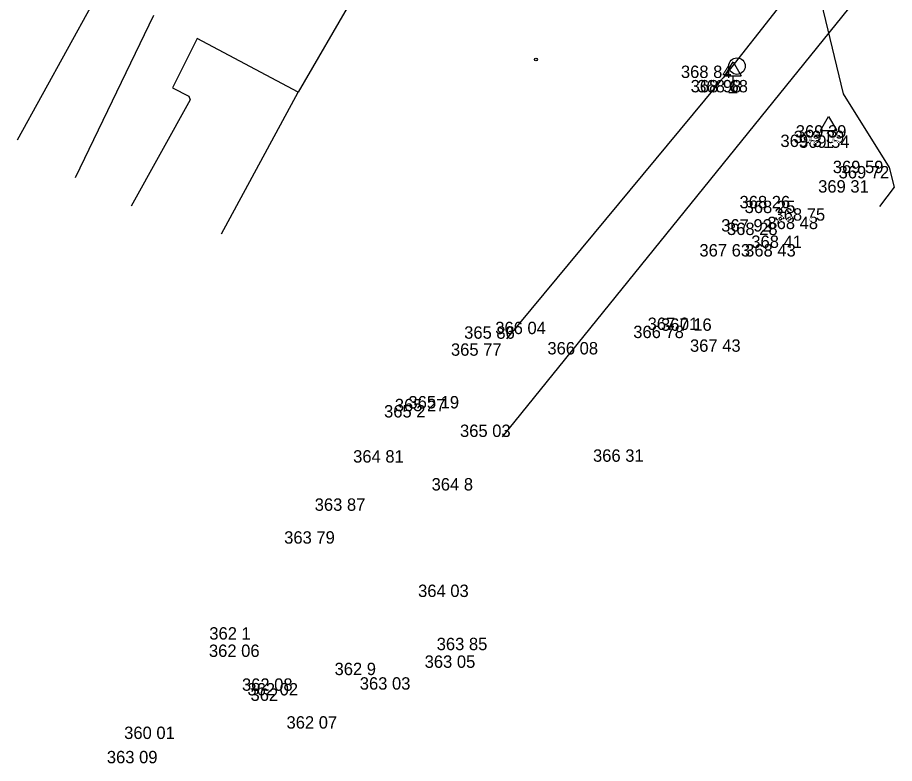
# Model space of a CAD drawing. Extents: x -688316 to -688024, y -973785 to -973591.
# Drawn here: x -688146.8 to -688093.7, y -973764.3 to -973719.2 of the extents above; entities that cross this region are included whole.
import ezdxf

# ---------------------------------------------------------------- set-up
doc = ezdxf.new("R2010")
doc.units = 0
for name, color, linetype in [('Vrstva 10', 7, 'Continuous'), ('Vrstva 27', 7, 'Continuous'), ('Vrstva 3', 7, 'Continuous'), ('Vrstva 34', 7, 'Continuous'), ('Vrstva 5', 7, 'Continuous'), ('Vrstva 58', 7, 'Continuous')]:
    doc.layers.add(name, color=color, linetype=linetype)

# ---------------------------------------------------------------- blocks, each defined once
blk = doc.blocks.new('B_NESP')
at = {"layer": 'Vrstva 58'}
blk.add_circle((0, 0), 0.875, dxfattribs=at)
blk = doc.blocks.new('DZ')
at = {"layer": 'Vrstva 34'}
for p, q in [((-5, 10), (0, 18.5)), ((0, 18.5), (5, 10)), ((-5, 10), (5, 10)), ((0, 0), (0, 10)), ((-2.49, 0), (2.49, 0))]:
    blk.add_line(p, q, dxfattribs=at)
blk = doc.blocks.new('SAK')
at = {"layer": 'Vrstva 27'}
blk.add_circle((0, 0), 5, dxfattribs=at)

msp = doc.modelspace()

# ---------------------------------------------------------------- linework, layer by layer
at = {"layer": 'Vrstva 10'}
msp.add_line((-688117.48, -973744.56), (-688096.49, -973718.61), dxfattribs=at)
at = {"layer": 'Vrstva 3'}
for points in [[(-688094.03, -973728.25), (-688096.82, -973723.78), (-688098.3, -973717.64), (-688099.11, -973714.05), (-688102.09, -973711.56)], [(-688094.03, -973728.25), (-688096.82, -973723.78), (-688098.3, -973717.64), (-688099.11, -973714.05), (-688102.09, -973711.56)], [(-688094.03, -973728.25), (-688096.82, -973723.78), (-688098.3, -973717.64), (-688099.11, -973714.05), (-688102.09, -973711.56)], [(-688094.03, -973728.25), (-688096.82, -973723.78), (-688098.3, -973717.64), (-688099.11, -973714.05), (-688102.09, -973711.56)], [(-688094.62, -973730.61), (-688093.73, -973729.44), (-688094.03, -973728.25)], [(-688094.62, -973730.61), (-688093.73, -973729.44), (-688094.03, -973728.25)], [(-688094.62, -973730.61), (-688093.73, -973729.44), (-688094.03, -973728.25)], [(-688094.62, -973730.61), (-688093.73, -973729.44), (-688094.03, -973728.25)]]:
    msp.add_lwpolyline(points, dxfattribs=at)
at = {"layer": 'Vrstva 5'}
for p, q in [((-688118.65, -973704.4), (-688129.85, -973723.67)), ((-688146.85, -973726.56), (-688142.31, -973718.32)), ((-688138.61, -973719.03), (-688143.36, -973728.87)), ((-688135.96, -973720.43), (-688137.47, -973723.41)), ((-688129.85, -973723.67), (-688135.96, -973720.43)), ((-688137.47, -973723.41), (-688136.48, -973723.93)), ((-688136.48, -973723.93), (-688136.4, -973724.15)), ((-688134.5, -973732.26), (-688129.85, -973723.67)), ((-688136.4, -973724.15), (-688139.97, -973730.58))]:
    msp.add_line(p, q, dxfattribs=at)
msp.add_lwpolyline([(-688100.74, -973717.32), (-688100.7, -973717.61), (-688100.61, -973718.36), (-688104.1, -973722.82), (-688104.28, -973723.02), (-688104.45, -973723.22), (-688117.23, -973738.61)], dxfattribs=at)

# ---------------------------------------------------------------- block references
at = {"layer": 'Vrstva 27', "xscale": 0.1, "yscale": 0.10000000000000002}
msp.add_blockref('SAK', (-688103.27, -973722.1), dxfattribs=at)
at = {"layer": 'Vrstva 34', "xscale": 0.1, "yscale": 0.10000000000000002}
for p in [(-688103.51, -973723.69), (-688103.51, -973723.69), (-688103.51, -973723.69), (-688103.51, -973723.69), (-688097.72, -973727), (-688097.72, -973727), (-688097.72, -973727), (-688097.72, -973727)]:
    msp.add_blockref('DZ', p, dxfattribs=at)
at = {"layer": 'Vrstva 58', "xscale": 0.1, "yscale": 0.10000000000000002}
msp.add_blockref('B_NESP', (-688115.45, -973721.7), dxfattribs=at)
msp.add_blockref('B_NESP', (-688115.45, -973721.7), dxfattribs=at)
msp.add_blockref('B_NESP', (-688115.45, -973721.7), dxfattribs=at)
msp.add_blockref('B_NESP', (-688115.45, -973721.7), dxfattribs=at)

# ---------------------------------------------------------------- texts
at = {"layer": 'Vrstva 3'}
for s, p in [('368 84 ', (-688106.666, -973722.82)), ('368 84 ', (-688106.666, -973722.82)), ('368 84 ', (-688106.666, -973722.82)), ('368 84 ', (-688106.666, -973722.82)), ('368 84 ', (-688106.666, -973722.82)), ('368 84 ', (-688106.666, -973722.82)), ('368 84 ', (-688106.666, -973722.82)), ('368 98 ', (-688106.076, -973723.69)), ('368 98 ', (-688106.076, -973723.69)), ('368 98 ', (-688106.076, -973723.69)), ('368 98 ', (-688106.076, -973723.69)), ('368 98 ', (-688106.076, -973723.69)), ('368 98 ', (-688106.076, -973723.69)), ('368 98 ', (-688106.076, -973723.69)), ('368 68 ', (-688105.675, -973723.69)), ('368 68 ', (-688105.675, -973723.69)), ('368 68 ', (-688105.675, -973723.69)), ('368 68 ', (-688105.675, -973723.69)), ('368 68 ', (-688105.675, -973723.69)), ('368 68 ', (-688105.675, -973723.69)), ('368 68 ', (-688105.675, -973723.69)), ('369 39 ', (-688099.708, -973726.43)), ('369 39 ', (-688099.708, -973726.43)), ('369 39 ', (-688099.708, -973726.43)), ('369 39 ', (-688099.708, -973726.43)), ('369 39 ', (-688099.708, -973726.43)), ('369 39 ', (-688099.708, -973726.43)), ('369 39 ', (-688099.708, -973726.43)), ('369 3  ', (-688100.637, -973727)), ('369 3  ', (-688100.637, -973727)), ('369 3  ', (-688100.637, -973727)), ('369 3  ', (-688100.637, -973727)), ('369 3  ', (-688100.637, -973727)), ('369 3  ', (-688100.637, -973727)), ('369 3  ', (-688100.637, -973727)), ('369 39 ', (-688099.838, -973726.76)), ('369 39 ', (-688099.838, -973726.76)), ('369 39 ', (-688099.838, -973726.76)), ('369 39 ', (-688099.838, -973726.76)), ('369 39 ', (-688099.838, -973726.76)), ('369 39 ', (-688099.838, -973726.76)), ('369 39 ', (-688099.838, -973726.76)), ('369 54 ', (-688099.516, -973727.05)), ('369 54 ', (-688099.516, -973727.05)), ('369 54 ', (-688099.516, -973727.05)), ('369 54 ', (-688099.516, -973727.05)), ('369 54 ', (-688099.516, -973727.05)), ('369 54 ', (-688099.516, -973727.05)), ('369 54 ', (-688099.516, -973727.05)), ('369 59 ', (-688097.466, -973728.58)), ('369 59 ', (-688097.466, -973728.58)), ('369 59 ', (-688097.466, -973728.58)), ('369 59 ', (-688097.466, -973728.58)), ('369 59 ', (-688097.466, -973728.58)), ('369 59 ', (-688097.466, -973728.58)), ('369 59 ', (-688097.466, -973728.58)), ('369 72 ', (-688097.116, -973728.9)), ('369 72 ', (-688097.116, -973728.9)), ('369 72 ', (-688097.116, -973728.9)), ('369 72 ', (-688097.116, -973728.9)), ('369 72 ', (-688097.116, -973728.9)), ('369 72 ', (-688097.116, -973728.9)), ('369 72 ', (-688097.116, -973728.9)), ('369 31 ', (-688098.353, -973729.76)), ('369 31 ', (-688098.353, -973729.76)), ('369 31 ', (-688098.353, -973729.76)), ('369 31 ', (-688098.353, -973729.76)), ('369 31 ', (-688098.353, -973729.76)), ('369 31 ', (-688098.353, -973729.76)), ('369 31 ', (-688098.353, -973729.76)), ('368 26 ', (-688103.116, -973730.71)), ('368 26 ', (-688103.116, -973730.71)), ('368 26 ', (-688103.116, -973730.71)), ('368 26 ', (-688103.116, -973730.71)), ('368 26 ', (-688103.116, -973730.71)), ('368 26 ', (-688103.116, -973730.71)), ('368 26 ', (-688103.116, -973730.71)), ('368 25 ', (-688102.806, -973731)), ('368 25 ', (-688102.806, -973731)), ('368 25 ', (-688102.806, -973731)), ('368 25 ', (-688102.806, -973731)), ('368 25 ', (-688102.806, -973731)), ('368 25 ', (-688102.806, -973731)), ('368 25 ', (-688102.806, -973731)), ('368 75 ', (-688100.996, -973731.46)), ('368 75 ', (-688100.996, -973731.46)), ('368 75 ', (-688100.996, -973731.46)), ('368 75 ', (-688100.996, -973731.46)), ('368 75 ', (-688100.996, -973731.46)), ('368 75 ', (-688100.996, -973731.46)), ('368 75 ', (-688100.996, -973731.46)), ('367 92 ', (-688104.226, -973732.12)), ('367 92 ', (-688104.226, -973732.12)), ('367 92 ', (-688104.226, -973732.12)), ('367 92 ', (-688104.226, -973732.12)), ('367 92 ', (-688104.226, -973732.12)), ('367 92 ', (-688104.226, -973732.12)), ('367 92 ', (-688104.226, -973732.12)), ('368 48 ', (-688101.426, -973731.97)), ('368 48 ', (-688101.426, -973731.97)), ('368 48 ', (-688101.426, -973731.97)), ('368 48 ', (-688101.426, -973731.97)), ('368 48 ', (-688101.426, -973731.97)), ('368 48 ', (-688101.426, -973731.97)), ('368 48 ', (-688101.426, -973731.97)), ('368 28 ', (-688103.876, -973732.33)), ('368 28 ', (-688103.876, -973732.33)), ('368 28 ', (-688103.876, -973732.33)), ('368 28 ', (-688103.876, -973732.33)), ('368 28 ', (-688103.876, -973732.33)), ('368 28 ', (-688103.876, -973732.33)), ('368 28 ', (-688103.876, -973732.33)), ('368 41 ', (-688102.401, -973733.11)), ('368 41 ', (-688102.401, -973733.11)), ('368 41 ', (-688102.401, -973733.11)), ('368 41 ', (-688102.401, -973733.11)), ('368 41 ', (-688102.401, -973733.11)), ('368 41 ', (-688102.401, -973733.11)), ('368 41 ', (-688102.401, -973733.11)), ('367 63 ', (-688105.545, -973733.63)), ('367 63 ', (-688105.545, -973733.63)), ('367 63 ', (-688105.545, -973733.63)), ('367 63 ', (-688105.545, -973733.63)), ('367 63 ', (-688105.545, -973733.63)), ('367 63 ', (-688105.545, -973733.63)), ('367 63 ', (-688105.545, -973733.63)), ('368 43 ', (-688102.776, -973733.63)), ('368 43 ', (-688102.776, -973733.63)), ('368 43 ', (-688102.776, -973733.63)), ('368 43 ', (-688102.776, -973733.63)), ('368 43 ', (-688102.776, -973733.63)), ('368 43 ', (-688102.776, -973733.63)), ('368 43 ', (-688102.776, -973733.63)), ('367 01 ', (-688108.681, -973738.08)), ('367 01 ', (-688108.681, -973738.08)), ('367 01 ', (-688108.681, -973738.08)), ('367 01 ', (-688108.681, -973738.08)), ('367 01 ', (-688108.681, -973738.08)), ('367 01 ', (-688108.681, -973738.08)), ('367 01 ', (-688108.681, -973738.08)), ('367 16 ', (-688107.871, -973738.13)), ('367 16 ', (-688107.871, -973738.13)), ('367 16 ', (-688107.871, -973738.13)), ('367 16 ', (-688107.871, -973738.13)), ('367 16 ', (-688107.871, -973738.13)), ('367 16 ', (-688107.871, -973738.13)), ('367 16 ', (-688107.871, -973738.13)), ('365 86 ', (-688119.796, -973738.61)), ('365 86 ', (-688119.796, -973738.61)), ('365 86 ', (-688119.796, -973738.61)), ('365 86 ', (-688119.796, -973738.61)), ('365 86 ', (-688119.796, -973738.61)), ('365 86 ', (-688119.796, -973738.61)), ('365 86 ', (-688119.796, -973738.61)), ('366 04 ', (-688117.913, -973738.33)), ('366 04 ', (-688117.913, -973738.33)), ('366 04 ', (-688117.913, -973738.33)), ('366 04 ', (-688117.913, -973738.33)), ('366 04 ', (-688117.913, -973738.33)), ('366 04 ', (-688117.913, -973738.33)), ('366 04 ', (-688117.913, -973738.33)), ('366 78 ', (-688109.553, -973738.57)), ('366 78 ', (-688109.553, -973738.57)), ('366 78 ', (-688109.553, -973738.57)), ('366 78 ', (-688109.553, -973738.57)), ('366 78 ', (-688109.553, -973738.57)), ('366 78 ', (-688109.553, -973738.57)), ('366 78 ', (-688109.553, -973738.57)), ('365 77 ', (-688120.596, -973739.64)), ('365 77 ', (-688120.596, -973739.64)), ('365 77 ', (-688120.596, -973739.64)), ('365 77 ', (-688120.596, -973739.64)), ('365 77 ', (-688120.596, -973739.64)), ('365 77 ', (-688120.596, -973739.64)), ('365 77 ', (-688120.596, -973739.64)), ('366 08 ', (-688114.753, -973739.56)), ('366 08 ', (-688114.753, -973739.56)), ('366 08 ', (-688114.753, -973739.56)), ('366 08 ', (-688114.753, -973739.56)), ('366 08 ', (-688114.753, -973739.56)), ('366 08 ', (-688114.753, -973739.56)), ('366 08 ', (-688114.753, -973739.56)), ('367 43 ', (-688106.116, -973739.4)), ('367 43 ', (-688106.116, -973739.4)), ('367 43 ', (-688106.116, -973739.4)), ('367 43 ', (-688106.116, -973739.4)), ('367 43 ', (-688106.116, -973739.4)), ('367 43 ', (-688106.116, -973739.4)), ('367 43 ', (-688106.116, -973739.4)), ('365 19 ', (-688123.171, -973742.83)), ('365 19 ', (-688123.171, -973742.83)), ('365 19 ', (-688123.171, -973742.83)), ('365 19 ', (-688123.171, -973742.83)), ('365 19 ', (-688123.171, -973742.83)), ('365 19 ', (-688123.171, -973742.83)), ('365 19 ', (-688123.171, -973742.83)), ('365 2  ', (-688124.647, -973743.38)), ('365 2  ', (-688124.647, -973743.38)), ('365 2  ', (-688124.647, -973743.38)), ('365 2  ', (-688124.647, -973743.38)), ('365 2  ', (-688124.647, -973743.38)), ('365 2  ', (-688124.647, -973743.38)), ('365 2  ', (-688124.647, -973743.38)), ('365 27 ', (-688123.996, -973743)), ('365 27 ', (-688123.996, -973743)), ('365 27 ', (-688123.996, -973743)), ('365 27 ', (-688123.996, -973743)), ('365 27 ', (-688123.996, -973743)), ('365 27 ', (-688123.996, -973743)), ('365 27 ', (-688123.996, -973743)), ('365 03 ', (-688120.046, -973744.56)), ('365 03 ', (-688120.046, -973744.56)), ('365 03 ', (-688120.046, -973744.56)), ('365 03 ', (-688120.046, -973744.56)), ('365 03 ', (-688120.046, -973744.56)), ('365 03 ', (-688120.046, -973744.56)), ('365 03 ', (-688120.046, -973744.56)), ('364 81 ', (-688126.521, -973746.11)), ('364 81 ', (-688126.521, -973746.11)), ('364 81 ', (-688126.521, -973746.11)), ('364 81 ', (-688126.521, -973746.11)), ('364 81 ', (-688126.521, -973746.11)), ('364 81 ', (-688126.521, -973746.11)), ('364 81 ', (-688126.521, -973746.11)), ('366 31 ', (-688111.991, -973746.06)), ('366 31 ', (-688111.991, -973746.06)), ('366 31 ', (-688111.991, -973746.06)), ('366 31 ', (-688111.991, -973746.06)), ('366 31 ', (-688111.991, -973746.06)), ('366 31 ', (-688111.991, -973746.06)), ('366 31 ', (-688111.991, -973746.06)), ('364 8  ', (-688121.767, -973747.8)), ('364 8  ', (-688121.767, -973747.8)), ('364 8  ', (-688121.767, -973747.8)), ('364 8  ', (-688121.767, -973747.8)), ('364 8  ', (-688121.767, -973747.8)), ('364 8  ', (-688121.767, -973747.8)), ('364 8  ', (-688121.767, -973747.8)), ('363 87 ', (-688128.849, -973749.03)), ('363 87 ', (-688128.849, -973749.03)), ('363 87 ', (-688128.849, -973749.03)), ('363 87 ', (-688128.849, -973749.03)), ('363 87 ', (-688128.849, -973749.03)), ('363 87 ', (-688128.849, -973749.03)), ('363 87 ', (-688128.849, -973749.03)), ('363 79 ', (-688130.699, -973751.02)), ('363 79 ', (-688130.699, -973751.02)), ('363 79 ', (-688130.699, -973751.02)), ('363 79 ', (-688130.699, -973751.02)), ('363 79 ', (-688130.699, -973751.02)), ('363 79 ', (-688130.699, -973751.02)), ('363 79 ', (-688130.699, -973751.02)), ('364 03 ', (-688122.586, -973754.25)), ('364 03 ', (-688122.586, -973754.25)), ('364 03 ', (-688122.586, -973754.25)), ('364 03 ', (-688122.586, -973754.25)), ('364 03 ', (-688122.586, -973754.25)), ('364 03 ', (-688122.586, -973754.25)), ('364 03 ', (-688122.586, -973754.25)), ('362 1  ', (-688135.233, -973756.83)), ('362 1  ', (-688135.233, -973756.83)), ('362 1  ', (-688135.233, -973756.83)), ('362 1  ', (-688135.233, -973756.83)), ('362 1  ', (-688135.233, -973756.83)), ('362 1  ', (-688135.233, -973756.83)), ('362 1  ', (-688135.233, -973756.83)), ('363 85 ', (-688121.459, -973757.47)), ('363 85 ', (-688121.459, -973757.47)), ('363 85 ', (-688121.459, -973757.47)), ('363 85 ', (-688121.459, -973757.47)), ('363 85 ', (-688121.459, -973757.47)), ('363 85 ', (-688121.459, -973757.47)), ('363 85 ', (-688121.459, -973757.47)), ('362 06 ', (-688135.256, -973757.88)), ('362 06 ', (-688135.256, -973757.88)), ('362 06 ', (-688135.256, -973757.88)), ('362 06 ', (-688135.256, -973757.88)), ('362 06 ', (-688135.256, -973757.88)), ('362 06 ', (-688135.256, -973757.88)), ('362 06 ', (-688135.256, -973757.88)), ('363 05 ', (-688122.189, -973758.54)), ('363 05 ', (-688122.189, -973758.54)), ('363 05 ', (-688122.189, -973758.54)), ('363 05 ', (-688122.189, -973758.54)), ('363 05 ', (-688122.189, -973758.54)), ('363 05 ', (-688122.189, -973758.54)), ('363 05 ', (-688122.189, -973758.54)), ('362 9  ', (-688127.647, -973758.98)), ('362 9  ', (-688127.647, -973758.98)), ('362 9  ', (-688127.647, -973758.98)), ('362 9  ', (-688127.647, -973758.98)), ('362 9  ', (-688127.647, -973758.98)), ('362 9  ', (-688127.647, -973758.98)), ('362 9  ', (-688127.647, -973758.98)), ('362 08 ', (-688133.256, -973759.93)), ('362 08 ', (-688133.256, -973759.93)), ('362 08 ', (-688133.256, -973759.93)), ('362 08 ', (-688133.256, -973759.93)), ('362 08 ', (-688133.256, -973759.93)), ('362 08 ', (-688133.256, -973759.93)), ('362 08 ', (-688133.256, -973759.93)), ('363 03 ', (-688126.119, -973759.86)), ('363 03 ', (-688126.119, -973759.86)), ('363 03 ', (-688126.119, -973759.86)), ('363 03 ', (-688126.119, -973759.86)), ('363 03 ', (-688126.119, -973759.86)), ('363 03 ', (-688126.119, -973759.86)), ('363 03 ', (-688126.119, -973759.86)), ('362 02 ', (-688132.926, -973760.21)), ('362 02 ', (-688132.926, -973760.21)), ('362 02 ', (-688132.926, -973760.21)), ('362 02 ', (-688132.926, -973760.21)), ('362 02 ', (-688132.926, -973760.21)), ('362 02 ', (-688132.926, -973760.21)), ('362 02 ', (-688132.926, -973760.21)), ('362    ', (-688132.737, -973760.54)), ('362    ', (-688132.737, -973760.54)), ('362    ', (-688132.737, -973760.54)), ('362    ', (-688132.737, -973760.54)), ('362    ', (-688132.737, -973760.54)), ('362    ', (-688132.737, -973760.54)), ('362    ', (-688132.737, -973760.54)), ('362 07 ', (-688130.556, -973762.22)), ('362 07 ', (-688130.556, -973762.22)), ('362 07 ', (-688130.556, -973762.22)), ('362 07 ', (-688130.556, -973762.22)), ('362 07 ', (-688130.556, -973762.22)), ('362 07 ', (-688130.556, -973762.22)), ('362 07 ', (-688130.556, -973762.22)), ('360 01 ', (-688140.391, -973762.85)), ('360 01 ', (-688140.391, -973762.85)), ('360 01 ', (-688140.391, -973762.85)), ('360 01 ', (-688140.391, -973762.85)), ('360 01 ', (-688140.391, -973762.85)), ('360 01 ', (-688140.391, -973762.85)), ('360 01 ', (-688140.391, -973762.85)), ('363 09 ', (-688141.439, -973764.32)), ('363 09 ', (-688141.439, -973764.32)), ('363 09 ', (-688141.439, -973764.32)), ('363 09 ', (-688141.439, -973764.32)), ('363 09 ', (-688141.439, -973764.32)), ('363 09 ', (-688141.439, -973764.32)), ('363 09 ', (-688141.439, -973764.32))]:
    msp.add_text(s, height=0.75, dxfattribs=at).set_placement(p)

doc.saveas('drawing.dxf')
